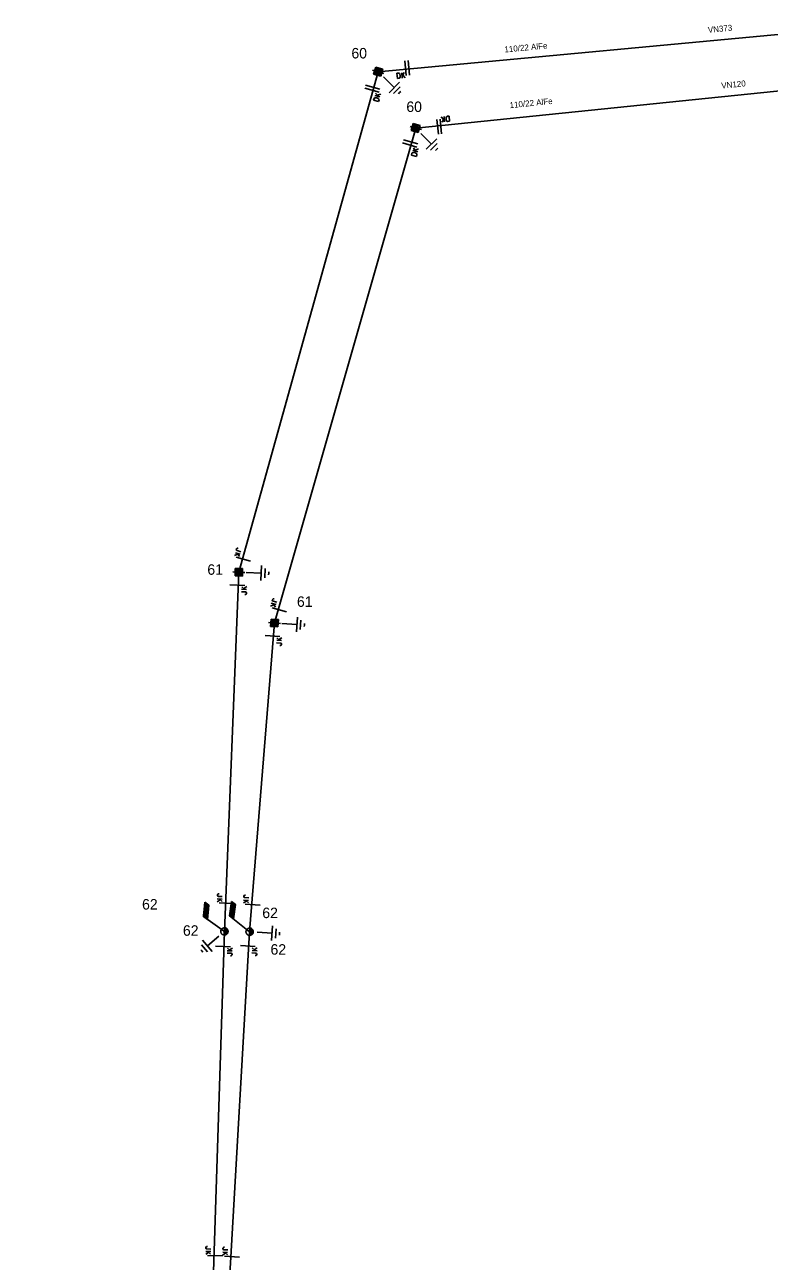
# Model space of a CAD drawing. Extents: x -540340 to -537226, y -1183949 to -1180375.
# Drawn here: x -540045.7 to -539921.3, y -1183409.6 to -1183202.9 of the extents above; entities that cross this region are included whole.
import ezdxf

# ---------------------------------------------------------------- set-up
doc = ezdxf.new("R2010")
doc.units = 0
for name, color, linetype in [('Default', 7, 'Continuous'), ('Vrstva 1', 7, 'Continuous'), ('Vrstva 11', 7, 'Continuous'), ('Vrstva 12', 7, 'Continuous'), ('Vrstva 13', 7, 'Continuous'), ('Vrstva 14', 7, 'Continuous'), ('Vrstva 15', 7, 'Continuous'), ('Vrstva 18', 7, 'Continuous'), ('Vrstva 2', 7, 'Continuous'), ('Vrstva 3', 7, 'Continuous')]:
    doc.layers.add(name, color=color, linetype=linetype)

# ---------------------------------------------------------------- blocks, each defined once
blk = doc.blocks.new('VN850')
at = {"layer": 'Vrstva 15'}
for points in [[(-0.56, 1.43), (-0.56, -1.07)], [(-0.01, 1.43), (-0.01, -1.07)], [(-2.09, -0.54), (-1.78, -0.54)], [(-2.09, -1.41), (-2.09, -0.54)], [(-1.78, -1.41), (-2.09, -1.41)], [(-1.78, -0.54), (-1.66, -0.6)], [(-1.67, -1.35), (-1.78, -1.41)], [(-1.59, -1.2), (-1.67, -1.35)], [(-1.66, -0.6), (-1.59, -0.75)], [(-1.59, -0.75), (-1.55, -0.96)], [(-1.55, -0.96), (-1.59, -1.2)], [(-1.26, -0.54), (-1.26, -1.41)], [(-0.85, -0.54), (-1.26, -1.09)], [(-1.13, -0.92), (-0.77, -1.41)]]:
    blk.add_lwpolyline(points, dxfattribs=at)
blk = doc.blocks.new('VN840')
at = {"layer": 'Vrstva 15'}
for points in [[(-0.01, 1.41), (-0.01, -1.09)], [(-1.51, -1.24), (-1.51, -1.15)], [(-1.48, -1.35), (-1.51, -1.24)], [(-1.33, -1.42), (-1.48, -1.35)], [(-1.27, -1.42), (-1.33, -1.42)], [(-1.13, -1.35), (-1.27, -1.42)], [(-1.09, -1.24), (-1.13, -1.35)], [(-1.09, -0.59), (-1.09, -1.24)], [(-0.68, -0.59), (-0.68, -1.42)], [(-0.68, -1.11), (-0.27, -0.59)], [(-0.54, -0.94), (-0.2, -1.42)]]:
    blk.add_lwpolyline(points, dxfattribs=at)
blk = doc.blocks.new('VN440')
at = {"layer": 'Vrstva 2'}
for points in [[(1.22, 0), (1.21, 0.13), (1.19, 0.25), (1.16, 0.38), (1.11, 0.5), (1.05, 0.61), (0.98, 0.72), (0.9, 0.82), (0.81, 0.91), (0.71, 0.99), (0.6, 1.06), (0.49, 1.12), (0.37, 1.16), (0.25, 1.2), (0.12, 1.22), (-0.01, 1.22), (-0.14, 1.22), (-0.26, 1.2), (-0.39, 1.16), (-0.51, 1.12), (-0.62, 1.06), (-0.73, 0.99), (-0.83, 0.91), (-0.92, 0.82), (-1, 0.72), (-1.07, 0.61), (-1.13, 0.5), (-1.18, 0.38), (-1.21, 0.25), (-1.23, 0.13), (-1.24, 0), (-1.23, -0.13), (-1.21, -0.26), (-1.18, -0.38), (-1.13, -0.5), (-1.07, -0.62), (-1, -0.73), (-0.92, -0.83), (-0.83, -0.92), (-0.73, -1), (-0.62, -1.07), (-0.51, -1.13), (-0.39, -1.17), (-0.26, -1.2), (-0.14, -1.23), (-0.01, -1.23), (0.12, -1.23), (0.25, -1.2), (0.37, -1.17), (0.49, -1.13), (0.6, -1.07), (0.71, -1), (0.81, -0.92), (0.9, -0.83), (0.98, -0.73), (1.05, -0.62), (1.11, -0.5), (1.16, -0.38), (1.19, -0.26), (1.21, -0.13), (1.22, 0)], [(-1.24, 0), (1.22, 0)], [(-1.18, -0.34), (1.1, -0.34)], [(-1.01, -0.63), (0.97, -0.63)], [(-0.74, -0.92), (0.68, -0.92)]]:
    blk.add_lwpolyline(points, dxfattribs=at)
blk = doc.blocks.new('VN810')
at = {"layer": 'Vrstva 14'}
for points in [[(0, -1.25), (0, -3.75)], [(1.25, -3.75), (-1.25, -3.75)], [(0.77, -4.37), (-0.8, -4.37)], [(0, -5), (-0.25, -5)], [(0.27, -5), (0, -5)]]:
    blk.add_lwpolyline(points, dxfattribs=at)
blk = doc.blocks.new('VN001')
at = {"layer": 'Default'}
for p, q in [((1.73, 3.03), (4.14, 3.03)), ((1.76, 3.08), (4.17, 3.08)), ((1.79, 3.13), (4.2, 3.13)), ((1.82, 3.18), (4.23, 3.18)), ((1.85, 3.23), (4.26, 3.23)), ((1.87, 3.28), (4.29, 3.28)), ((1.9, 3.33), (4.32, 3.33)), ((1.93, 3.38), (4.35, 3.38)), ((1.96, 3.43), (4.37, 3.43)), ((1.99, 3.48), (4.4, 3.48)), ((2.02, 3.53), (4.43, 3.53)), ((2.05, 3.58), (4.46, 3.58)), ((2.07, 3.63), (4.49, 3.63)), ((2.1, 3.68), (4.52, 3.68)), ((2.13, 3.73), (2.54, 3.73))]:
    blk.add_line(p, q, dxfattribs=at)
blk.add_lwpolyline([(2.13, 3.73), (0, 0)], dxfattribs=at)
blk.add_lwpolyline([(4.55, 3.73), (2.13, 3.73), (1.7, 2.98), (4.12, 2.99)], close=True, dxfattribs=at)
blk = doc.blocks.new('VN470')
at = {"layer": 'Vrstva 2'}
for points in [[(-1.23, 1.22), (1.23, 1.22)], [(-1.23, -1.23), (-1.23, 1.22)], [(-0.92, 0.9), (0.92, 0.9)], [(-0.92, -0.95), (-0.92, 0.9)], [(-0.61, 0.61), (0.61, 0.61)], [(-0.61, -0.62), (-0.61, 0.61)], [(-0.31, -0.27), (-0.31, 0.34)], [(-0.31, 0.34), (0.31, 0.34)], [(0, 1.22), (0, 1.97)], [(0.31, 0.34), (0.31, -0.27)], [(0.61, 0.61), (0.61, -0.62)], [(0.92, 0.9), (0.92, -0.95)], [(1.23, 1.22), (1.23, -1.23)], [(1.23, -1.23), (-1.23, -1.23)], [(0.92, -0.95), (-0.92, -0.95)], [(0.61, -0.62), (-0.61, -0.62)], [(0.31, -0.27), (-0.31, -0.27)], [(0, -1.23), (0, -1.98)]]:
    blk.add_lwpolyline(points, dxfattribs=at)

msp = doc.modelspace()

# ---------------------------------------------------------------- linework, layer by layer
at = {"layer": 'Vrstva 1'}
for points in [[(-540012.36, -1183354.43), (-540009.96, -1183294.39), (-539986.67, -1183210.74), (-539910.31, -1183203.61)], [(-539904.86, -1183212.44), (-539980.4, -1183220.14), (-540003.99, -1183302.87), (-540008.15, -1183354.48)], [(-540012.36, -1183354.43), (-540014.17, -1183411.34), (-540028.85, -1183530.04), (-540045.72, -1183647.03)], [(-540008.15, -1183354.48), (-540011.44, -1183411.77), (-540026.2, -1183530.3), (-540043.23, -1183647.3)]]:
    msp.add_lwpolyline(points, dxfattribs=at)

# ---------------------------------------------------------------- block references
at = {"layer": 'Vrstva 11'}
for p, rotation in [((-540012.36, -1183354.43), 84.61605272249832), ((-540008.15, -1183354.48), 81.48321104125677)]:
    msp.add_blockref('VN001', p, dxfattribs=dict(at, rotation=rotation))
at = {"layer": 'Vrstva 13'}
for name, p, xscale, yscale, rotation in [('VN470', (-539986.67, -1183210.74), 0.5, 0.5, 74.09066667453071), ('VN470', (-539980.4, -1183220.14), 0.49999999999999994, 0.5000000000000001, 74.007597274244), ('VN470', (-540009.96, -1183294.39), 0.49999999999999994, 0.49999999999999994, 87.9287444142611), ('VN470', (-540003.99, -1183302.87), 0.5, 0.49999999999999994, 85.94546111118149), ('VN440', (-540012.36, -1183354.43), 0.5, 0.5, 87.76985553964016), ('VN440', (-540008.15, -1183354.48), 0.5, 0.5000000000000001, 86.1933361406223)]:
    msp.add_blockref(name, p, dxfattribs=dict(at, xscale=xscale, yscale=yscale, rotation=rotation))
at = {"layer": 'Vrstva 15'}
for p, rotation in [((-539986.67, -1183210.74), 45.70227779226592), ((-539980.4, -1183220.14), 44.25360546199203), ((-540009.96, -1183294.39), 87.92874448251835), ((-540003.99, -1183302.87), 85.94546111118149), ((-540008.15, -1183354.48), 86.1933361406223), ((-540012.36, -1183354.43), -49.45121385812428)]:
    msp.add_blockref('VN810', p, dxfattribs=dict(at, rotation=rotation))
at = {"layer": 'Vrstva 18'}
for name, p, rotation in [('VN850', (-539981.52, -1183210.26), 5.337066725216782), ('VN850', (-539987.4, -1183213.34), 74.56577217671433), ('VN850', (-539976.77, -1183219.77), -174.18496391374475), ('VN850', (-539981.07, -1183222.5), 74.00756939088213), ('VN840', (-540009.34, -1183292.17), -105.43422778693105), ('VN840', (-540010.05, -1183296.55), 87.92942494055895), ('VN840', (-540003.35, -1183300.63), -105.99243060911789), ('VN840', (-540004.17, -1183305.05), 85.94597781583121), ('VN840', (-540012.17, -1183349.72), -92.25707495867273), ('VN840', (-540007.79, -1183349.97), -94.18905552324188), ('VN840', (-540012.45, -1183356.96), 87.95846395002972), ('VN840', (-540008.29, -1183356.89), 86.30751940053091), ('VN840', (-540014.08, -1183408.65), -91.81863880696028), ('VN840', (-540011.27, -1183408.81), -93.28678055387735)]:
    msp.add_blockref(name, p, dxfattribs=dict(at, rotation=rotation))

# ---------------------------------------------------------------- texts
at = {"layer": 'Vrstva 12'}
for p in [(-540026.12, -1183350.78), (-540006.03, -1183352.21)]:
    msp.add_text('62', height=1.75, dxfattribs=at).set_placement(p)
at = {"layer": 'Vrstva 14'}
for s, p in [('60', (-539991.14, -1183208.51)), ('60', (-539981.96, -1183217.46)), ('61', (-540015.21, -1183294.82)), ('61', (-540000.24, -1183300.18)), ('62', (-540019.29, -1183355.16)), ('62', (-540004.66, -1183358.32))]:
    msp.add_text(s, height=1.75, dxfattribs=at).set_placement(p)
at = {"layer": 'Vrstva 2'}
for rotation, p in [(5.337, (-539965.53, -1183207.52)), (5.815, (-539964.66, -1183216.84))]:
    msp.add_text('110/22 AlFe', height=1, rotation=rotation, dxfattribs=at).set_placement(p)
at = {"layer": 'Vrstva 3'}
for s, rotation, p in [('VN373', 5.337, (-539931.54, -1183204.24)), ('VN120', 5.815, (-539929.29, -1183213.57))]:
    msp.add_text(s, height=1, rotation=rotation, dxfattribs=at).set_placement(p)

doc.saveas('drawing.dxf')
